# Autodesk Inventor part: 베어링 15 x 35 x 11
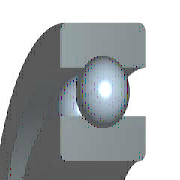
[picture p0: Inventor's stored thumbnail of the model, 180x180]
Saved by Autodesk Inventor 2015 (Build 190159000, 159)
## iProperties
Created: 2012-02
Part Number: 베어링 15 x 35 x 11
Material: 강철, 연강
Description: 깊은 그루브 볼 베어링
Document SubType Name: Modeling
Standard: KS B 2023
Designer: mduedu
Standards Organization: KS
Language: ko-KR
Size Designation: 6202 - 15 x 35 x 11
Categories: <MemberInstance><Categories><Category DisplayName="샤프트 부품" InternalName="7f7aeb1f-a693-4053-b835-cee3144e0d98" Mnemonic="SHFT"><Category DisplayName="베어링" Inter
Density: 1 g/cm^3
Appearance: 강철
IsCustomPart: 1
Author: mduedu
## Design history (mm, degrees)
sketch "스케치" dims "d0" = 5.2 (= -0.26 x WD + 0.26 x BD)
  geometry: L1 (2.9, 12.5)-(8.1, 12.5); L2 (5.5, 12.5)-(5.5, 9.9); L3 (5.5, 12.5)-(5.5, 15.1); L4 (3.568, 10.76)-(0, 10.76); L5 (0, 7.5)-(11, 7.5); L6 (3.568, 14.24)-(0, 14.24); L7 (0, 17.5)-(11, 17.5); L8 (11, 7.5)-(11, 10.76); L9 (7.432, 10.76)-(11, 10.76); L10 (7.432, 14.24)-(11, 14.24); L11 (11, 17.5)-(11, 14.24); L12 (-1.4, 0)-(8.4, 0) reference; L13 (0, -0.3)-(0, 5.3) reference
  constraints: 22 end point, 4 point on line, 2 collinear, 2 perpendicular, 2 symmetric about line, 1 midpoint, 1 parallel, 14 other
  dimensions: "d9" = 15 diameter of L5 L12 (= WD); "d11" = 35 diameter of L7 L12 (= BD); "d12" = 11 distance between parallel lines of L8 L13 (= KB); "d13" = 21.52 diameter of L9 L12 (= 0.326 x BD + 0.674 x WD)
revolve "본체" stored, may be unused: angle "d6" = 90 deg
revolve "볼" stored, may be unused: angle "d7" = 90 deg
pattern_circular "IDS_ARRAYBALL[SIMPL:T]" dims angle "d3" = 360 deg
body "Solid1"
fillet "모깎기1" dims "d1" = 0.6 (= KRS)
other parameters: "WD" = 15 [user parameter; used in 5 equation terms], "BD" = 35 [user parameter; used in 5 equation terms], "KB" = 11 [user parameter; used in 1 equation term], "KRS" = 0.6 [user parameter; used in 1 equation term], "d4" = 0, "d5" = 0, "d8" = 0, "d14" = 0, "d15" = 0, "BBA" = 0 [user parameter], "BC0" = 3750000 [user parameter], "BC" = 7800000 [user parameter], "BR" = 17.5 (= 0.5 x BD) [user parameter], "WR" = 7.5 (= 0.5 x WD) [user parameter]
